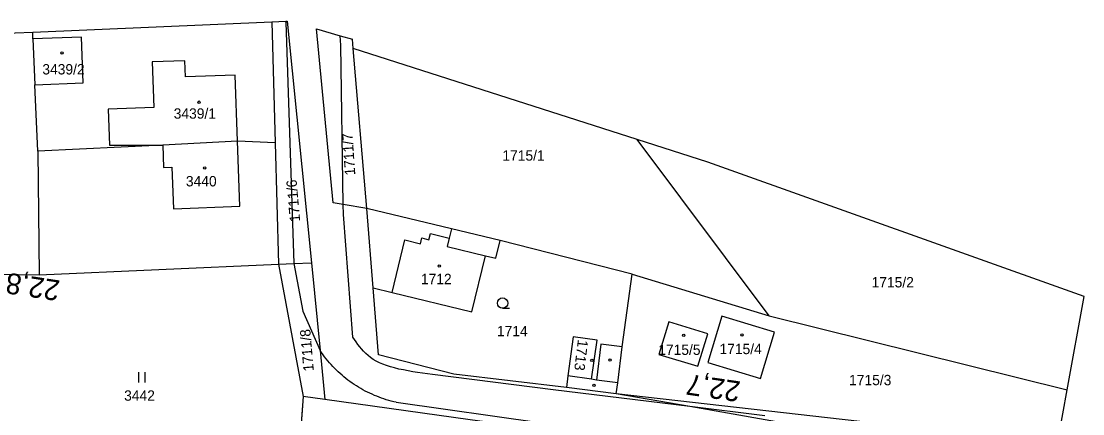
# Model space of a CAD drawing. Extents: x -757895 to -757311, y -1060303 to -1059942.
# Drawn here: x -757679.5 to -757525.5, y -1060109.2 to -1060052.3 of the extents above; entities that cross this region are included whole.
import ezdxf

# ---------------------------------------------------------------- set-up
doc = ezdxf.new("R2010")
doc.units = 0
for name, color, linetype in [('_hektaky', 7, 'Continuous'), ('Vrstva 55', 7, 'Continuous'), ('Vrstva 56', 7, 'Continuous'), ('Vrstva 57', 7, 'Continuous'), ('Vrstva 58', 7, 'Continuous'), ('Vrstva 59', 7, 'Continuous')]:
    doc.layers.add(name, color=color, linetype=linetype)

msp = doc.modelspace()

# ---------------------------------------------------------------- linework, layer by layer
at = {"layer": 'Vrstva 55'}
for p, q in [((-757677.84, -1060053.89), (-757643.18, -1060052.41)), ((-757643.18, -1060052.41), (-757642.66, -1060069.92)), ((-757643.18, -1060052.41), (-757642.66, -1060069.92)), ((-757640.91, -1060052.31), (-757637.42, -1060087.32)), ((-757688.39, -1060054.34), (-757677.84, -1060053.89)), ((-757677.8, -1060054.85), (-757677.84, -1060053.89)), ((-757677.8, -1060054.85), (-757677.51, -1060061.51)), ((-757631.34, -1060056.24), (-757631.45, -1060054.91)), ((-757629.39, -1060079.46), (-757631.34, -1060056.24)), ((-757590.19, -1060069.45), (-757631.34, -1060056.24)), ((-757677.1, -1060071.14), (-757677.51, -1060061.51)), ((-757642.66, -1060069.92), (-757642.17, -1060087.53)), ((-757642.66, -1060069.92), (-757642.17, -1060087.53)), ((-757571.04, -1060094.99), (-757590.19, -1060069.45)), ((-757579.91, -1060072.75), (-757590.19, -1060069.45)), ((-757677.1, -1060071.14), (-757676.88, -1060089.06)), ((-757525.35, -1060092.2), (-757579.91, -1060072.75)), ((-757628.47, -1060090.94), (-757629.39, -1060079.46)), ((-757590.9, -1060088.98), (-757610.05, -1060084.09)), ((-757676.88, -1060089.06), (-757642.17, -1060087.53)), ((-757642.17, -1060087.53), (-757638.59, -1060106.69)), ((-757642.17, -1060087.53), (-757638.59, -1060106.69)), ((-757689.45, -1060088.87), (-757676.88, -1060089.06)), ((-757592.34, -1060099.49), (-757590.9, -1060088.98)), ((-757590.9, -1060088.98), (-757571.04, -1060094.99)), ((-757527.8, -1060105.72), (-757525.35, -1060092.2)), ((-757571.04, -1060094.99), (-757527.8, -1060105.72)), ((-757592.99, -1060104.69), (-757592.34, -1060099.49)), ((-757593.23, -1060106.29), (-757592.99, -1060104.69)), ((-757638.59, -1060106.69), (-757639.93, -1060124.17)), ((-757638.59, -1060106.69), (-757639.93, -1060124.17)), ((-757635.45, -1060107.13), (-757638.59, -1060106.69)), ((-757593.23, -1060106.29), (-757600.41, -1060105.4)), ((-757530.66, -1060121.48), (-757527.8, -1060105.72))]:
    msp.add_line(p, q, dxfattribs=at)
for points in [[(-757643.18, -1060052.41), (-757641.12, -1060052.32), (-757640.91, -1060052.31)], [(-757643.18, -1060052.41), (-757642.66, -1060069.92), (-757642.17, -1060087.53), (-757638.59, -1060106.69), (-757639.93, -1060124.17), (-757639.03, -1060128.02), (-757637.9, -1060132.49), (-757634.26, -1060145.96), (-757630.94, -1060158.73), (-757631.18, -1060185.19), (-757631.2, -1060187.35)], [(-757629.39, -1060079.46), (-757632.79, -1060078.88), (-757634.26, -1060078.63), (-757636.66, -1060053.43), (-757633.26, -1060054.4), (-757631.45, -1060054.91)], [(-757677.51, -1060061.51), (-757670.5, -1060061.23), (-757670.77, -1060054.6), (-757677.8, -1060054.85)], [(-757642.66, -1060069.92), (-757648.14, -1060069.67), (-757658.97, -1060070.25), (-757677.1, -1060071.14)], [(-757610.05, -1060084.09), (-757617.11, -1060082.38), (-757629.39, -1060079.46)], [(-757628.47, -1060090.94), (-757625.72, -1060091.6), (-757614.14, -1060094.41), (-757612.17, -1060086.29), (-757610.67, -1060086.66), (-757610.05, -1060084.09)], [(-757642.17, -1060087.53), (-757639.97, -1060087.39), (-757637.42, -1060087.32)], [(-757637.42, -1060087.32), (-757636.16, -1060100.03), (-757635.45, -1060107.13)], [(-757600.41, -1060105.4), (-757616.74, -1060103.46), (-757627.69, -1060100.66), (-757628.47, -1060090.94)], [(-757581.36, -1060102.3), (-757579.91, -1060097.6), (-757585.56, -1060095.88), (-757587.03, -1060100.59), (-757581.36, -1060102.3)], [(-757579.94, -1060101.75), (-757572.27, -1060104.08), (-757570.24, -1060097.38), (-757577.88, -1060095.03), (-757579.94, -1060101.75)], [(-757592.34, -1060099.49), (-757595.44, -1060099.1), (-757596.09, -1060104.3), (-757596.77, -1060104.18), (-757595.99, -1060098.5), (-757599.43, -1060098.03), (-757600.22, -1060103.7), (-757600.41, -1060105.4)], [(-757538.3, -1060115.83), (-757542.65, -1060115.17), (-757582.51, -1060108.15), (-757593.23, -1060106.29)], [(-757538.3, -1060115.83), (-757541.05, -1060113.79), (-757553.6, -1060110.8), (-757593.23, -1060106.29)], [(-757604.11, -1060111.45), (-757614.37, -1060110.07), (-757635.45, -1060107.13)]]:
    msp.add_lwpolyline(points, dxfattribs=at)
at = {"layer": 'Vrstva 56'}
for p, q in [((-757641.12, -1060052.42), (-757641.12, -1060052.32)), ((-757641.12, -1060052.42), (-757639.97, -1060087.39)), ((-757633.15, -1060055.76), (-757633.26, -1060054.4)), ((-757632.79, -1060078.88), (-757633.15, -1060055.76)), ((-757655.79, -1060058.03), (-757660.5, -1060058.19)), ((-757660.5, -1060058.19), (-757660.27, -1060064.81)), ((-757655.69, -1060060.37), (-757655.79, -1060058.03)), ((-757648.49, -1060060.1), (-757655.69, -1060060.37)), ((-757648.14, -1060069.67), (-757648.49, -1060060.1)), ((-757660.27, -1060064.81), (-757666.88, -1060065.04)), ((-757666.88, -1060065.04), (-757666.7, -1060070.26)), ((-757647.79, -1060079.11), (-757648.14, -1060069.67)), ((-757666.7, -1060070.26), (-757658.97, -1060070.25)), ((-757658.97, -1060070.25), (-757658.85, -1060073.5)), ((-757658.85, -1060073.5), (-757657.65, -1060073.45)), ((-757657.65, -1060073.45), (-757657.42, -1060079.47)), ((-757657.42, -1060079.47), (-757647.79, -1060079.11)), ((-757632.77, -1060080.29), (-757632.79, -1060078.88)), ((-757631.4, -1060098.08), (-757632.77, -1060080.29)), ((-757621.6, -1060084.55), (-757621.4, -1060083.71)), ((-757621.4, -1060083.71), (-757620.38, -1060083.96)), ((-757620.38, -1060083.96), (-757620.16, -1060083.08)), ((-757620.16, -1060083.08), (-757617.44, -1060083.74)), ((-757617.44, -1060083.74), (-757617.73, -1060084.95)), ((-757617.11, -1060082.38), (-757617.44, -1060083.74)), ((-757625.72, -1060091.6), (-757623.88, -1060084)), ((-757623.88, -1060084), (-757621.6, -1060084.55)), ((-757617.73, -1060084.95), (-757612.17, -1060086.29)), ((-757639.97, -1060087.39), (-757638.66, -1060094.33)), ((-757638.66, -1060094.33), (-757636.16, -1060100.03)), ((-757602.33, -1060105.73), (-757619.86, -1060103.51)), ((-757596.77, -1060104.18), (-757600.22, -1060103.7)), ((-757592.99, -1060104.69), (-757596.09, -1060104.3)), ((-757582.51, -1060108.15), (-757602.33, -1060105.73)), ((-757625.12, -1060107.53), (-757604, -1060110.48)), ((-757571.64, -1060109.48), (-757582.51, -1060108.15))]:
    msp.add_line(p, q, dxfattribs=at)
for points in [[(-757619.86, -1060103.51), (-757620.58, -1060103.41), (-757621.3, -1060103.31), (-757622.01, -1060103.2), (-757622.71, -1060103.09), (-757623.4, -1060102.97), (-757624.07, -1060102.84), (-757624.72, -1060102.71), (-757625.35, -1060102.55), (-757625.95, -1060102.39), (-757626.52, -1060102.21), (-757627.06, -1060102.02), (-757627.56, -1060101.8), (-757628.02, -1060101.56), (-757628.45, -1060101.31), (-757628.84, -1060101.03), (-757629.2, -1060100.75), (-757629.53, -1060100.44), (-757629.84, -1060100.13), (-757630.13, -1060099.8), (-757630.41, -1060099.47), (-757630.67, -1060099.13), (-757630.92, -1060098.78), (-757631.16, -1060098.43), (-757631.4, -1060098.08)], [(-757625.12, -1060107.53), (-757625.48, -1060107.45), (-757625.84, -1060107.36), (-757626.2, -1060107.26), (-757626.55, -1060107.15), (-757626.9, -1060107.04), (-757627.25, -1060106.92), (-757627.6, -1060106.79), (-757627.94, -1060106.66), (-757628.28, -1060106.52), (-757628.62, -1060106.37), (-757628.96, -1060106.22), (-757629.29, -1060106.06), (-757629.62, -1060105.89), (-757629.95, -1060105.71), (-757630.27, -1060105.53), (-757630.58, -1060105.34), (-757630.9, -1060105.15), (-757631.21, -1060104.95), (-757631.51, -1060104.74), (-757631.82, -1060104.52), (-757632.11, -1060104.3), (-757632.41, -1060104.08), (-757632.69, -1060103.85), (-757632.97, -1060103.61), (-757633.25, -1060103.36), (-757633.53, -1060103.11), (-757633.79, -1060102.86), (-757634.06, -1060102.6), (-757634.31, -1060102.33), (-757634.56, -1060102.06), (-757634.81, -1060101.79), (-757635.05, -1060101.51), (-757635.28, -1060101.22), (-757635.51, -1060100.93), (-757635.73, -1060100.63), (-757635.95, -1060100.33), (-757636.16, -1060100.03)]]:
    msp.add_lwpolyline(points, dxfattribs=at)
at = {"layer": 'Vrstva 58'}
for p, q in [((-757609.69, -1060093.89), (-757608.69, -1060093.89)), ((-757662.51, -1060103.14), (-757662.51, -1060104.64)), ((-757661.51, -1060104.64), (-757661.51, -1060103.14))]:
    msp.add_line(p, q, dxfattribs=at)
msp.add_circle((-757609.69, -1060093.14), 0.75, dxfattribs=at)
at = {"layer": 'Vrstva 59'}
for centre in [(-757673.58, -1060056.91), (-757653.71, -1060064.04), (-757652.89, -1060073.57), (-757618.88, -1060087.78), (-757574.97, -1060097.77), (-757583.42, -1060097.83), (-757596.74, -1060101.43), (-757594.1, -1060101.41), (-757596.44, -1060105.07)]:
    msp.add_circle(centre, 0.175, dxfattribs=at)

# ---------------------------------------------------------------- texts
at = {"layer": '_hektaky'}
for s, rotation, p in [('22,8', 171.4001, (-757673.76, -1060089.9)), ('22,7', 171.7816, (-757575.06, -1060104.53))]:
    msp.add_text(s, height=3, rotation=rotation, dxfattribs=at).set_placement(p)
at = {"layer": 'Vrstva 57'}
for s, p in [('3439/2', (-757676.44, -1060060.02)), ('3439/1', (-757657.39, -1060066.43)), ('1715/1', (-757609.72, -1060072.51)), ('3440', (-757655.62, -1060076.24)), ('1712', (-757621.54, -1060090.41)), ('1715/2', (-757556.17, -1060090.88)), ('1714', (-757610.51, -1060097.96)), ('1715/5', (-757587.11, -1060100.66)), ('1715/4', (-757578.23, -1060100.55)), ('1715/3', (-757559.43, -1060105.05)), ('3442', (-757664.58, -1060107.3))]:
    msp.add_text(s, height=1.5, dxfattribs=at).set_placement(p)
for s, rotation, p in [('1711/7', 94, (-757631.04, -1060074.59)), ('1711/6', 95, (-757639.04, -1060081.32)), ('1711/8', 95, (-757637.06, -1060102.98)), ('1713', 263, (-757598.76, -1060098.4))]:
    msp.add_text(s, height=1.5, rotation=rotation, dxfattribs=at).set_placement(p)

doc.saveas('drawing.dxf')
